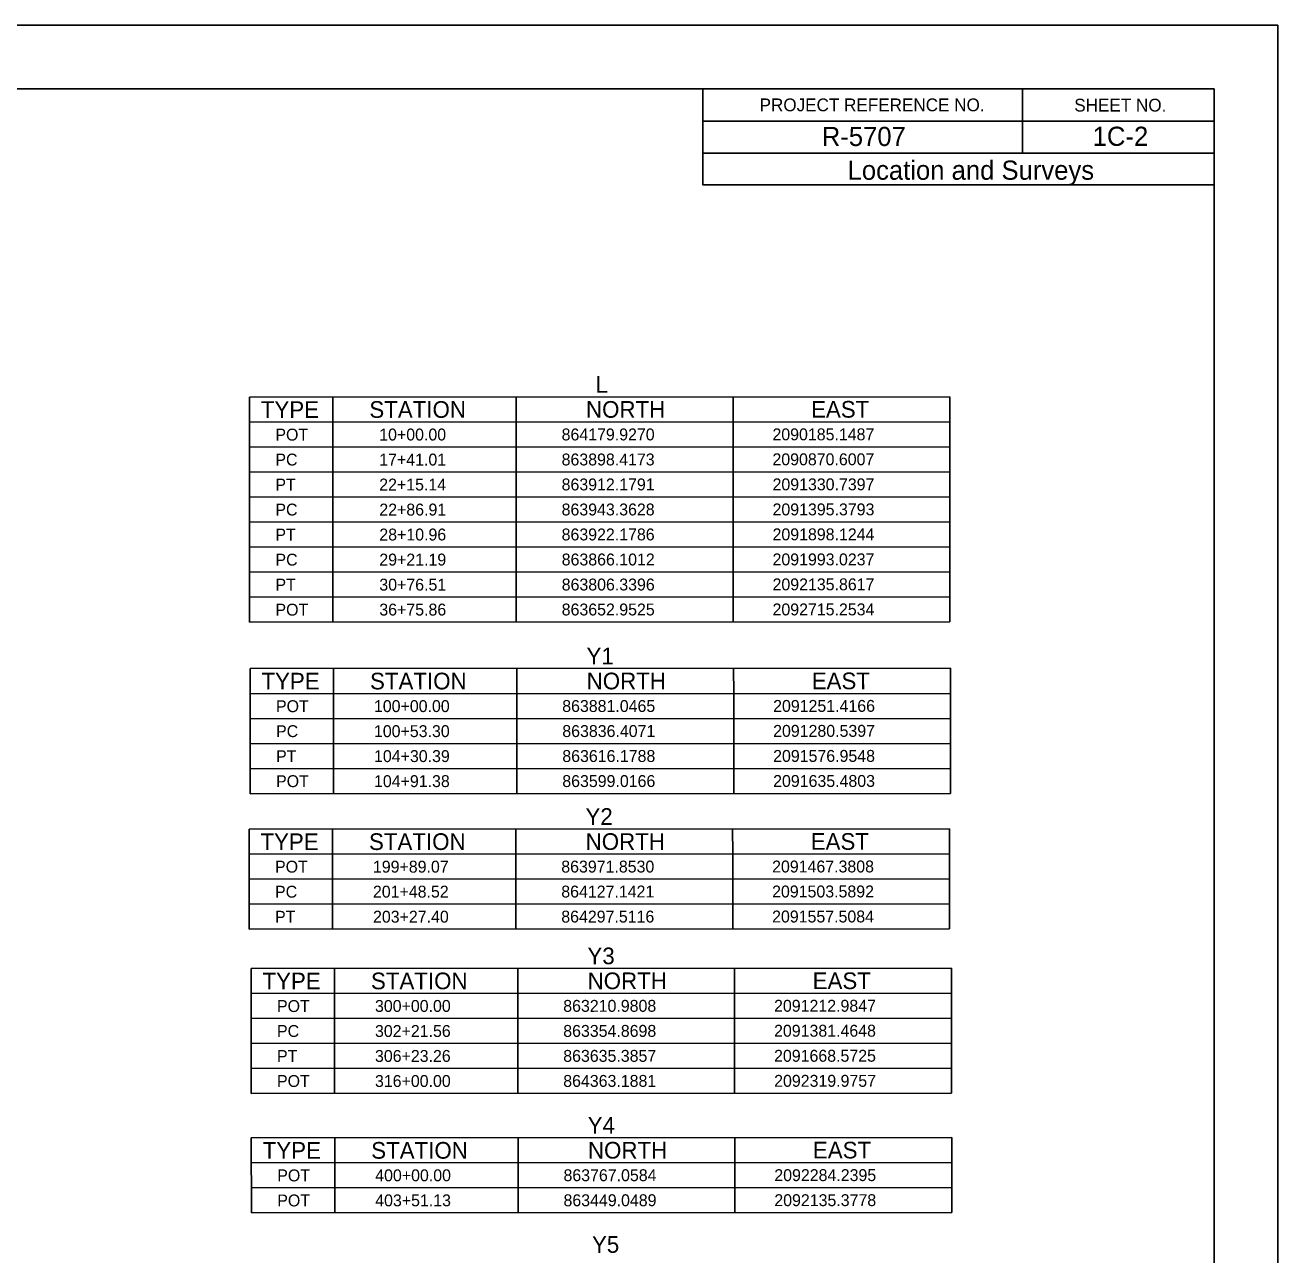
# Model space of a CAD drawing. Extents: x 2093228 to 2098328, y 861854 to 865154.
# Drawn here: x 2096858 to 2098328, y 863710 to 865154 of the extents above; entities that cross this region are included whole.
import ezdxf

# ---------------------------------------------------------------- set-up
doc = ezdxf.new("R2010")
doc.units = 0
for name, color, linetype in [('CTL Sheet Notes CELL', 7, 'Continuous'), ('CTL Sheet Table Cell', 7, 'Continuous'), ('CTL Sheet Text', 7, 'Continuous'), ('Sheet Data Field CELL', 7, 'Continuous'), ('Sheet Plan CELL', 7, 'Continuous'), ('Sheet Plot Border Inside CELL', 7, 'Continuous')]:
    doc.layers.add(name, color=color, linetype=linetype)

msp = doc.modelspace()

# ---------------------------------------------------------------- linework, layer by layer
at = {"layer": 'CTL Sheet Table Cell'}
for p, q in [((2097121, 864717.4), (2097943.2, 864717.8)), ((2097121, 864717.4), (2097121, 864688)), ((2097218.9, 864717.4), (2097218.9, 864688.1)), ((2097434.2, 864717.5), (2097434.2, 864688.2)), ((2097688.7, 864717.6), (2097688.7, 864688.3)), ((2097943.2, 864717.8), (2097943.2, 864688.4)), ((2097121, 864688), (2097943.2, 864688.4)), ((2097121, 864688), (2097121.1, 864658.6)), ((2097218.9, 864688.1), (2097218.9, 864658.7)), ((2097434.2, 864688.2), (2097434.2, 864658.8)), ((2097688.7, 864688.3), (2097688.7, 864658.9)), ((2097943.2, 864688.4), (2097943.2, 864659)), ((2097121.1, 864658.6), (2097943.2, 864659)), ((2097121.1, 864658.6), (2097121.1, 864629.3)), ((2097218.9, 864658.7), (2097218.9, 864629.3)), ((2097434.2, 864658.8), (2097434.3, 864629.4)), ((2097688.7, 864658.9), (2097688.7, 864629.6)), ((2097943.2, 864659), (2097943.2, 864629.7)), ((2097121.1, 864629.3), (2097943.2, 864629.7)), ((2097121.1, 864629.3), (2097121.1, 864599.9)), ((2097218.9, 864629.3), (2097219, 864600)), ((2097434.3, 864629.4), (2097434.3, 864600.1)), ((2097688.7, 864629.6), (2097688.7, 864600.2)), ((2097943.2, 864629.7), (2097943.2, 864600.3)), ((2097121.1, 864599.9), (2097943.2, 864600.3)), ((2097121.1, 864599.9), (2097121.1, 864570.6)), ((2097219, 864600), (2097219, 864570.6)), ((2097434.3, 864600.1), (2097434.3, 864570.7)), ((2097688.7, 864600.2), (2097688.8, 864570.8)), ((2097943.2, 864600.3), (2097943.2, 864571)), ((2097121.1, 864570.6), (2097943.2, 864571)), ((2097121.1, 864570.6), (2097121.1, 864541.2)), ((2097219, 864570.6), (2097219, 864541.2)), ((2097434.3, 864570.7), (2097434.3, 864541.3)), ((2097688.8, 864570.8), (2097688.8, 864541.5)), ((2097943.2, 864571), (2097943.2, 864541.6)), ((2097121.1, 864541.2), (2097943.2, 864541.6)), ((2097121.1, 864541.2), (2097121.1, 864511.8)), ((2097219, 864541.2), (2097219, 864511.9)), ((2097434.3, 864541.3), (2097434.3, 864512)), ((2097688.8, 864541.5), (2097688.8, 864512.1)), ((2097943.2, 864541.6), (2097943.2, 864512.2)), ((2097121.1, 864511.8), (2097943.2, 864512.2)), ((2097121.1, 864511.8), (2097121.1, 864482.5)), ((2097219, 864511.9), (2097219, 864482.5)), ((2097434.3, 864512), (2097434.3, 864482.6)), ((2097688.8, 864512.1), (2097688.8, 864482.7)), ((2097943.2, 864512.2), (2097943.3, 864482.9)), ((2097121.1, 864482.5), (2097943.3, 864482.9)), ((2097121.1, 864482.5), (2097121.2, 864453.1)), ((2097219, 864482.5), (2097219, 864453.2)), ((2097434.3, 864482.6), (2097434.3, 864453.3)), ((2097688.8, 864482.7), (2097688.8, 864453.4)), ((2097943.3, 864482.9), (2097943.3, 864453.5)), ((2097121.2, 864453.1), (2097943.3, 864453.5)), ((2097121.8, 864398.6), (2097943.9, 864399)), ((2097121.8, 864398.6), (2097121.8, 864369.2)), ((2097219.7, 864398.6), (2097219.7, 864369.2)), ((2097435, 864398.7), (2097435, 864369.4)), ((2097689.4, 864398.8), (2097689.5, 864369.5)), ((2097943.9, 864399), (2097943.9, 864369.6)), ((2097121.8, 864369.2), (2097943.9, 864369.6)), ((2097121.8, 864369.2), (2097121.8, 864339.8)), ((2097219.7, 864369.2), (2097219.7, 864339.9)), ((2097435, 864369.4), (2097435, 864340)), ((2097689.5, 864369.5), (2097689.5, 864340.1)), ((2097943.9, 864369.6), (2097943.9, 864340.2)), ((2097121.8, 864339.8), (2097943.9, 864340.2)), ((2097121.8, 864339.8), (2097121.8, 864310.5)), ((2097219.7, 864339.9), (2097219.7, 864310.5)), ((2097435, 864340), (2097435, 864310.6)), ((2097689.5, 864340.1), (2097689.5, 864310.8)), ((2097943.9, 864340.2), (2097943.9, 864310.9)), ((2097121.8, 864310.5), (2097943.9, 864310.9)), ((2097121.8, 864310.5), (2097121.8, 864281.1)), ((2097219.7, 864310.5), (2097219.7, 864281.2)), ((2097435, 864310.6), (2097435, 864281.3)), ((2097689.5, 864310.8), (2097689.5, 864281.4)), ((2097943.9, 864310.9), (2097944, 864281.5)), ((2097121.8, 864281.1), (2097944, 864281.5)), ((2097121.8, 864281.1), (2097121.9, 864251.8)), ((2097219.7, 864281.2), (2097219.7, 864251.8)), ((2097435, 864281.3), (2097435, 864251.9)), ((2097689.5, 864281.4), (2097689.5, 864252)), ((2097944, 864281.5), (2097944, 864252.1)), ((2097121.9, 864251.8), (2097944, 864252.1)), ((2097120.6, 864210.1), (2097942.7, 864210.5)), ((2097120.6, 864210.1), (2097120.6, 864180.7)), ((2097218.5, 864210.1), (2097218.5, 864180.8)), ((2097433.8, 864210.2), (2097433.8, 864180.9)), ((2097688.2, 864210.4), (2097688.3, 864181)), ((2097942.7, 864210.5), (2097942.7, 864181.1)), ((2097120.6, 864180.7), (2097942.7, 864181.1)), ((2097120.6, 864180.7), (2097120.6, 864151.4)), ((2097218.5, 864180.8), (2097218.5, 864151.4)), ((2097433.8, 864180.9), (2097433.8, 864151.5)), ((2097688.3, 864181), (2097688.3, 864151.6)), ((2097942.7, 864181.1), (2097942.7, 864151.8)), ((2097120.6, 864151.4), (2097942.7, 864151.8)), ((2097120.6, 864151.4), (2097120.6, 864122)), ((2097218.5, 864151.4), (2097218.5, 864122)), ((2097433.8, 864151.5), (2097433.8, 864122.2)), ((2097688.3, 864151.6), (2097688.3, 864122.3)), ((2097942.7, 864151.8), (2097942.8, 864122.4)), ((2097120.6, 864122), (2097942.8, 864122.4)), ((2097120.6, 864122), (2097120.6, 864092.6)), ((2097218.5, 864122), (2097218.5, 864092.7)), ((2097433.8, 864122.2), (2097433.8, 864092.8)), ((2097688.3, 864122.3), (2097688.3, 864092.9)), ((2097942.8, 864122.4), (2097942.8, 864093)), ((2097120.6, 864092.6), (2097942.8, 864093)), ((2097122.9, 864046.6), (2097945, 864047)), ((2097122.9, 864046.6), (2097122.9, 864017.2)), ((2097220.8, 864046.6), (2097220.8, 864017.2)), ((2097436.1, 864046.7), (2097436.1, 864017.3)), ((2097690.6, 864046.8), (2097690.6, 864017.5)), ((2097945, 864047), (2097945.1, 864017.6)), ((2097122.9, 864017.2), (2097945.1, 864017.6)), ((2097122.9, 864017.2), (2097122.9, 863987.8)), ((2097220.8, 864017.2), (2097220.8, 863987.9)), ((2097436.1, 864017.3), (2097436.1, 863988)), ((2097690.6, 864017.5), (2097690.6, 863988.1)), ((2097945.1, 864017.6), (2097945.1, 863988.2)), ((2097122.9, 863987.8), (2097945.1, 863988.2)), ((2097122.9, 863987.8), (2097123, 863958.5)), ((2097220.8, 863987.9), (2097220.8, 863958.5)), ((2097436.1, 863988), (2097436.2, 863958.6)), ((2097690.6, 863988.1), (2097690.6, 863958.7)), ((2097945.1, 863988.2), (2097945.1, 863958.9)), ((2097123, 863958.5), (2097945.1, 863958.9)), ((2097123, 863958.5), (2097123, 863929.1)), ((2097220.8, 863958.5), (2097220.8, 863929.2)), ((2097436.2, 863958.6), (2097436.2, 863929.3)), ((2097690.6, 863958.7), (2097690.6, 863929.4)), ((2097945.1, 863958.9), (2097945.1, 863929.5)), ((2097123, 863929.1), (2097945.1, 863929.5)), ((2097123, 863929.1), (2097123, 863899.7)), ((2097220.8, 863929.2), (2097220.9, 863899.8)), ((2097436.2, 863929.3), (2097436.2, 863899.9)), ((2097690.6, 863929.4), (2097690.6, 863900)), ((2097945.1, 863929.5), (2097945.1, 863900.1)), ((2097123, 863899.7), (2097945.1, 863900.1)), ((2097123.2, 863847.7), (2097945.4, 863848.1)), ((2097123.2, 863847.7), (2097123.2, 863818.4)), ((2097221.1, 863847.8), (2097221.1, 863818.4)), ((2097436.4, 863847.9), (2097436.4, 863818.5)), ((2097690.9, 863848), (2097690.9, 863818.6)), ((2097945.4, 863848.1), (2097945.4, 863818.8)), ((2097123.2, 863818.4), (2097945.4, 863818.8)), ((2097123.2, 863818.4), (2097123.3, 863789)), ((2097221.1, 863818.4), (2097221.1, 863789.1)), ((2097436.4, 863818.5), (2097436.4, 863789.2)), ((2097690.9, 863818.6), (2097690.9, 863789.3)), ((2097945.4, 863818.8), (2097945.4, 863789.4)), ((2097123.3, 863789), (2097945.4, 863789.4)), ((2097123.3, 863789), (2097123.3, 863759.6)), ((2097221.1, 863789.1), (2097221.1, 863759.7)), ((2097436.4, 863789.2), (2097436.5, 863759.8)), ((2097690.9, 863789.3), (2097690.9, 863759.9)), ((2097945.4, 863789.4), (2097945.4, 863760)), ((2097123.3, 863759.6), (2097945.4, 863760))]:
    msp.add_line(p, q, dxfattribs=at)
at = {"layer": 'Sheet Plan CELL'}
for p, q in [((2098028.4, 865003.9), (2098028.4, 865079.1)), ((2097653.3, 865041.4), (2098253.4, 865041.4)), ((2097653.3, 865003.8), (2098253.4, 865003.9))]:
    msp.add_line(p, q, dxfattribs=at)
for points in [[(2093753.4, 865079.1), (2098253.4, 865079.1), (2098253.4, 861929.1), (2093753.4, 861929.1)], [(2097653.3, 865079.1), (2098253.4, 865079.1), (2098253.4, 864966.4), (2097653.3, 864966.4)]]:
    msp.add_lwpolyline(points, close=True, dxfattribs=at)
at = {"layer": 'Sheet Plot Border Inside CELL'}
msp.add_lwpolyline([(2098328.4, 865154.1), (2093228.4, 865154.1), (2093228.4, 861854.1), (2098328.4, 861854.1)], close=True, dxfattribs=at)

# ---------------------------------------------------------------- texts
at = {"layer": 'CTL Sheet Notes CELL'}
for s, height, p in [('L', 19.6, (2097527.3, 864722.5)), ('TYPE', 19.57, (2097134.4, 864692.9)), ('STATION', 19.57, (2097261.8, 864693)), ('NORTH', 19.57, (2097516.1, 864693.1)), ('EAST', 19.57, (2097780.3, 864693.2)), ('Y1', 19.57, (2097516.7, 864403.6)), ('TYPE', 19.57, (2097135.1, 864374.1)), ('STATION', 19.57, (2097262.6, 864374.2)), ('NORTH', 19.57, (2097516.9, 864374.3)), ('EAST', 19.57, (2097781.1, 864374.4)), ('Y2', 19.57, (2097515.5, 864215.2)), ('TYPE', 19.57, (2097133.9, 864185.6)), ('STATION', 19.57, (2097261.4, 864185.7)), ('NORTH', 19.57, (2097515.7, 864185.8)), ('EAST', 19.57, (2097779.9, 864185.9)), ('Y3', 19.57, (2097517.8, 864051.6)), ('TYPE', 19.57, (2097136.3, 864022.1)), ('STATION', 19.57, (2097263.7, 864022.2)), ('NORTH', 19.57, (2097518, 864022.3)), ('EAST', 19.57, (2097782.2, 864022.4)), ('Y4', 19.57, (2097518.1, 863852.8)), ('TYPE', 19.57, (2097136.6, 863823.3)), ('STATION', 19.57, (2097264, 863823.3)), ('NORTH', 19.57, (2097518.4, 863823.5)), ('EAST', 19.57, (2097782.5, 863823.6)), ('Y5', 19.57, (2097523.1, 863712.8))]:
    msp.add_text(s, height=height, rotation=0.0276, dxfattribs=at).set_placement(p)
at = {"layer": 'CTL Sheet Text'}
for s, height, p in [('POT', 13.98, (2097151.5, 864666.3)), ('10+00.00', 13.98, (2097273.4, 864666.4)), ('864179.9270', 13.982, (2097487.5, 864666.5)), ('2090185.1487', 13.982, (2097735, 864666.6)), ('PC ', 13.98, (2097151.5, 864637)), ('17+41.01', 13.98, (2097273.4, 864637)), ('863898.4173', 13.982, (2097487.5, 864637.1)), ('2090870.6007', 13.982, (2097735, 864637.3)), ('PT ', 13.98, (2097151.5, 864607.6)), ('22+15.14', 13.98, (2097273.4, 864607.7)), ('863912.1791', 13.982, (2097487.5, 864607.8)), ('2091330.7397', 13.982, (2097735.1, 864607.9)), ('PC ', 13.98, (2097151.5, 864578.3)), ('22+86.91', 13.98, (2097273.5, 864578.3)), ('863943.3628', 13.982, (2097487.5, 864578.4)), ('2091395.3793', 13.982, (2097735.1, 864578.5)), ('PT ', 13.98, (2097151.5, 864548.9)), ('28+10.96', 13.98, (2097273.5, 864549)), ('863922.1786', 13.982, (2097487.5, 864549.1)), ('2091898.1244', 13.982, (2097735.1, 864549.2)), ('PC ', 13.98, (2097151.6, 864519.5)), ('29+21.19', 13.98, (2097273.5, 864519.6)), ('863866.1012', 13.982, (2097487.6, 864519.7)), ('2091993.0237', 13.982, (2097735.1, 864519.8)), ('PT ', 13.98, (2097151.6, 864490.2)), ('30+76.51', 13.98, (2097273.5, 864490.2)), ('863806.3396', 13.982, (2097487.6, 864490.3)), ('2092135.8617', 13.982, (2097735.1, 864490.5)), ('POT', 13.98, (2097151.6, 864460.8)), ('36+75.86', 13.98, (2097273.5, 864460.9)), ('863652.9525', 13.982, (2097487.6, 864461)), ('2092715.2534', 13.982, (2097735.1, 864461.1)), ('POT', 13.98, (2097152.2, 864347.5)), ('100+00.00', 13.98, (2097267.2, 864347.6)), ('863881.0465', 13.982, (2097488.2, 864347.7)), ('2091251.4166', 13.982, (2097735.8, 864347.8)), ('PC ', 13.98, (2097152.3, 864318.2)), ('100+53.30', 13.98, (2097267.2, 864318.2)), ('863836.4071', 13.982, (2097488.3, 864318.3)), ('2091280.5397', 13.982, (2097735.8, 864318.5)), ('PT ', 13.98, (2097152.3, 864288.8)), ('104+30.39', 13.98, (2097267.3, 864288.9)), ('863616.1788', 13.982, (2097488.3, 864289)), ('2091576.9548', 13.982, (2097735.8, 864289.1)), ('POT', 13.98, (2097152.3, 864259.5)), ('104+91.38', 13.98, (2097267.3, 864259.5)), ('863599.0166', 13.982, (2097488.3, 864259.6)), ('2091635.4803', 13.982, (2097735.8, 864259.7)), ('POT', 13.98, (2097151.1, 864159.1)), ('199+89.07', 13.98, (2097266, 864159.1)), ('863971.8530', 13.982, (2097487.1, 864159.2)), ('2091467.3808', 13.982, (2097734.6, 864159.3)), ('PC ', 13.98, (2097151.1, 864129.7)), ('201+48.52', 13.98, (2097266, 864129.8)), ('864127.1421', 13.982, (2097487.1, 864129.9)), ('2091503.5892', 13.982, (2097734.6, 864130)), ('PT ', 13.98, (2097151.1, 864100.3)), ('203+27.40', 13.98, (2097266.1, 864100.4)), ('864297.5116', 13.982, (2097487.1, 864100.5)), ('2091557.5084', 13.982, (2097734.6, 864100.6)), ('POT', 13.98, (2097153.4, 863995.5)), ('300+00.00', 13.98, (2097268.4, 863995.6)), ('863210.9808', 13.982, (2097489.4, 863995.7)), ('2091212.9847', 13.982, (2097736.9, 863995.8)), ('PC ', 13.98, (2097153.4, 863966.2)), ('302+21.56', 13.98, (2097268.4, 863966.2)), ('863354.8698', 13.982, (2097489.4, 863966.3)), ('2091381.4648', 13.982, (2097736.9, 863966.5)), ('PT ', 13.98, (2097153.4, 863936.8)), ('306+23.26', 13.98, (2097268.4, 863936.9)), ('863635.3857', 13.982, (2097489.4, 863937)), ('2091668.5725', 13.982, (2097736.9, 863937.1)), ('POT', 13.98, (2097153.4, 863907.5)), ('316+00.00', 13.98, (2097268.4, 863907.5)), ('864363.1881', 13.982, (2097489.4, 863907.6)), ('2092319.9757', 13.982, (2097737, 863907.7)), ('400+00.00', 13.98, (2097268.7, 863796.8)), ('863767.0584', 13.982, (2097489.7, 863796.9)), ('2092284.2395', 13.982, (2097737.2, 863797)), ('POT', 13.98, (2097153.7, 863796.7)), ('403+51.13', 13.98, (2097268.7, 863767.4)), ('863449.0489', 13.982, (2097489.7, 863767.5)), ('2092135.3778', 13.982, (2097737.2, 863767.6)), ('POT', 13.98, (2097153.7, 863767.3))]:
    msp.add_text(s, height=height, rotation=0.0276, dxfattribs=at).set_placement(p)
at = {"layer": 'Sheet Data Field CELL'}
for s, p in [('R-5707', (2097792.9, 865012.1)), ('1C-2', (2098110.9, 865012.3))]:
    msp.add_text(s, height=22.5, rotation=0, dxfattribs=at).set_placement(p)
at = {"layer": 'Sheet Plan CELL'}
for s, height, p in [('PROJECT REFERENCE NO.', 15, (2097719.9, 865052.9)), ('SHEET NO.', 15, (2098089.3, 865052.6)), ('Location and Surveys', 22.5, (2097823.2, 864972.5))]:
    msp.add_text(s, height=height, rotation=0, dxfattribs=at).set_placement(p)

doc.saveas('drawing.dxf')
